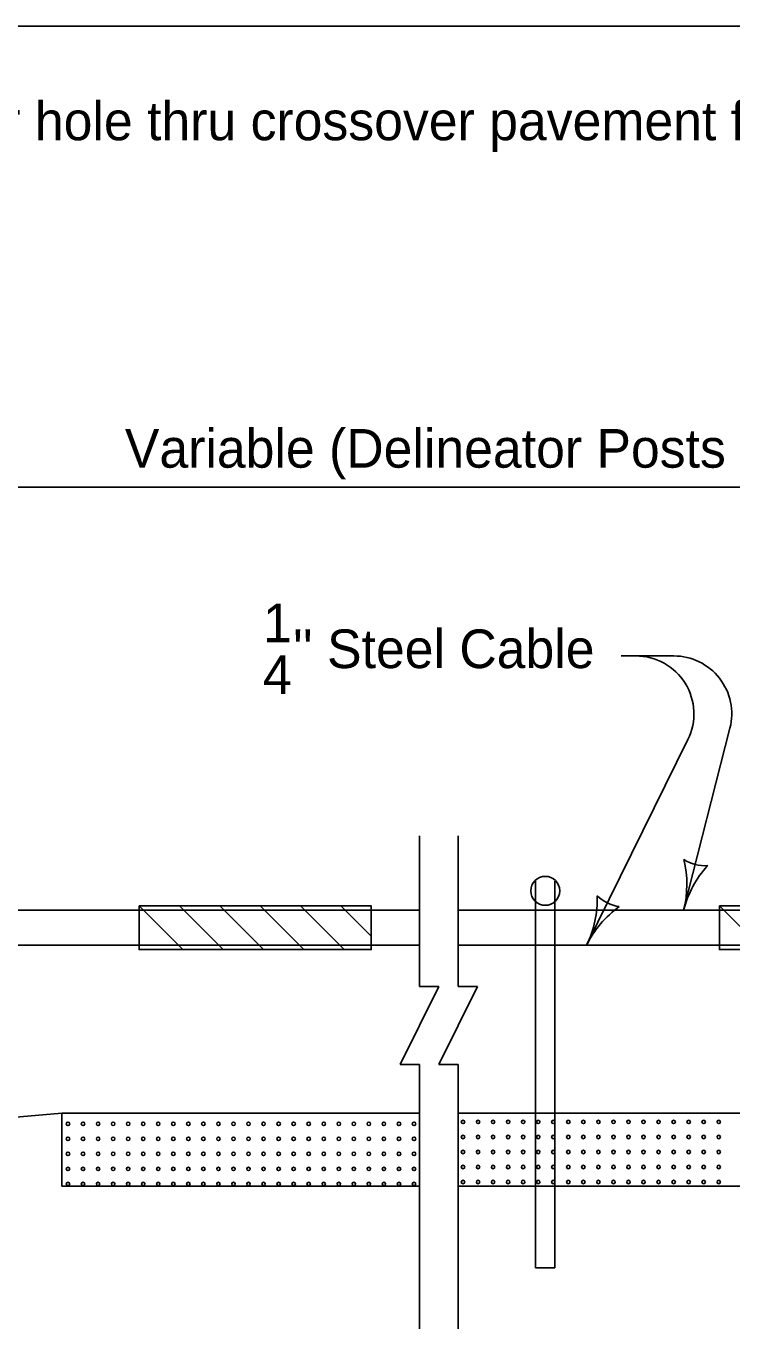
# Model space of a CAD drawing. Extents: x 228 to 3572, y -1307 to 1277.
# Drawn here: x 956 to 1248, y 35 to 575 of the extents above; entities that cross this region are included whole.
import ezdxf

# ---------------------------------------------------------------- set-up
doc = ezdxf.new("R2010")
doc.units = 0
doc.layers.add('dsnStdDimension', color=7, linetype='Continuous')
doc.layers.add('Level 2', color=7, linetype='Continuous')

msp = doc.modelspace()

# ---------------------------------------------------------------- linework, layer by layer
at = {"layer": 'dsnStdDimension'}
for p, q in [((690.89, 383.93), (2130.88, 383.93)), ((1202.29, 314.02), (1224.02, 314.02)), ((1228.12, 208.79), (1247.28, 284.11)), ((1187.96, 194.29), (1229.9, 279.42))]:
    msp.add_line(p, q, dxfattribs=at)
for centre, radius, start, end in [((1208.37, 290.02), 24, 333.7735, 90), ((1224.02, 290.02), 24, 345.7273, 90), ((1186.27, 219.43), 43.18, 345.7274, 13.7999), ((1269.97, 198.14), 43.18, 137.655, 165.7274), ((1237.05, 243.87), 16.68, 237.9941, 273.4608), ((1149.23, 213.37), 43.18, 333.7725, 1.8449), ((1203.96, 226.76), 16.68, 226.0391, 261.5058), ((1226.7, 175.2), 43.18, 125.7, 153.7725)]:
    msp.add_arc(centre, radius, start, end, dxfattribs=at)
at = {"layer": 'Level 2'}
for p, q in [((519.47, 574.71), (2276.26, 574.71)), ((1118.89, 239.58), (1118.89, 177.25)), ((1134.89, 239.58), (1134.89, 177.25)), ((1166.89, 220.79), (1166.89, 124.79)), ((1174.89, 220.79), (1174.89, 124.79)), ((1002.89, 210.54), (1020.99, 192.44)), ((1019.58, 210.54), (1037.68, 192.44)), ((1036.27, 210.54), (1054.37, 192.44)), ((1052.95, 210.54), (1071.05, 192.44)), ((1069.65, 210.54), (1087.75, 192.44)), ((1086.33, 210.54), (1098.87, 198)), ((458.89, 208.79), (1118.89, 208.79)), ((1134.89, 208.79), (1686.88, 208.79)), ((458.89, 194.29), (1118.89, 194.29)), ((1134.89, 194.29), (1686.88, 194.29)), ((1110.89, 144.94), (1126.89, 177.25)), ((1118.89, 177.25), (1126.89, 177.25)), ((1126.89, 144.94), (1142.89, 177.25)), ((1134.89, 177.25), (1142.89, 177.25)), ((1118.89, 144.94), (1110.89, 144.94)), ((1118.89, 144.94), (1118.89, 124.79)), ((1134.89, 144.94), (1126.89, 144.94)), ((1134.89, 144.94), (1134.89, 124.79)), ((970.89, 124.79), (810.89, 110.34)), ((970.89, 94.49), (970.89, 124.79)), ((970.89, 94.49), (970.89, 124.79)), ((970.89, 94.49), (970.89, 124.79)), ((970.89, 124.79), (1118.89, 124.79)), ((970.89, 124.79), (1118.89, 124.79)), ((1118.89, 124.79), (1118.89, 94.49)), ((1134.89, 94.49), (1134.89, 124.79)), ((1134.89, 124.79), (1686.88, 124.79)), ((1134.89, 124.79), (1686.88, 124.79)), ((1134.89, 124.79), (1686.88, 124.79)), ((1166.89, 124.79), (1166.89, 60.79)), ((1174.89, 124.79), (1174.89, 60.79)), ((1118.89, 94.49), (970.89, 94.49)), ((1118.89, 94.49), (1118.89, 35.46)), ((1134.89, 94.49), (1134.89, 35.46)), ((1686.88, 94.49), (1134.89, 94.49)), ((1166.89, 60.79), (1174.89, 60.79))]:
    msp.add_line(p, q, dxfattribs=at)
for points in [[(1002.89, 210.54), (1098.89, 210.54), (1098.89, 192.44), (1002.89, 192.44)], [(1002.89, 210.54), (1002.89, 192.44), (1020.99, 192.44)], [(1037.68, 192.44), (1054.37, 192.44), (1036.27, 210.54), (1019.58, 210.54)], [(1071.05, 192.44), (1087.75, 192.44), (1069.65, 210.54), (1052.95, 210.54)], [(1098.87, 198), (1098.87, 210.54), (1086.33, 210.54)], [(1242.89, 210.54), (1338.89, 210.54), (1338.89, 192.44), (1242.89, 192.44)], [(1242.89, 210.54), (1242.89, 192.44), (1260.99, 192.44)]]:
    msp.add_lwpolyline(points, close=True, dxfattribs=at)
for centre, radius in [((1170.89, 216.79), 6), ((973.48, 120.37), 0.711), ((979.71, 120.37), 0.711), ((985.93, 120.37), 0.711), ((992.15, 120.37), 0.711), ((998.37, 120.37), 0.711), ((1004.6, 120.37), 0.711), ((1010.82, 120.37), 0.711), ((1017.04, 120.37), 0.711), ((1023.26, 120.37), 0.711), ((1029.48, 120.37), 0.711), ((1035.71, 120.37), 0.711), ((1041.93, 120.37), 0.711), ((1048.15, 120.37), 0.711), ((1054.37, 120.37), 0.711), ((1060.6, 120.37), 0.711), ((1066.82, 120.37), 0.711), ((1073.04, 120.37), 0.711), ((1079.26, 120.37), 0.711), ((1085.49, 120.37), 0.711), ((1091.71, 120.37), 0.711), ((1097.93, 120.37), 0.711), ((1104.15, 120.37), 0.711), ((1110.38, 120.37), 0.711), ((1116.6, 120.37), 0.711), ((1136.87, 121.15), 0.711), ((1143.09, 121.15), 0.711), ((1149.31, 121.15), 0.711), ((1155.53, 121.15), 0.711), ((1161.76, 121.15), 0.711), ((1167.98, 121.15), 0.711), ((1174.2, 121.15), 0.711), ((1180.42, 121.15), 0.711), ((1186.64, 121.15), 0.711), ((1192.87, 121.15), 0.711), ((1199.09, 121.15), 0.711), ((1205.31, 121.15), 0.711), ((1211.53, 121.15), 0.711), ((1217.76, 121.15), 0.711), ((1223.98, 121.15), 0.711), ((1230.2, 121.15), 0.711), ((1236.42, 121.15), 0.711), ((1242.65, 121.15), 0.711), ((973.48, 114.14), 0.711), ((979.71, 114.14), 0.711), ((985.93, 114.14), 0.711), ((992.15, 114.14), 0.711), ((998.37, 114.14), 0.711), ((1004.6, 114.14), 0.711), ((1010.82, 114.14), 0.711), ((1017.04, 114.14), 0.711), ((1023.26, 114.14), 0.711), ((1029.48, 114.14), 0.711), ((1035.71, 114.14), 0.711), ((1041.93, 114.14), 0.711), ((1048.15, 114.14), 0.711), ((1054.37, 114.14), 0.711), ((1060.6, 114.14), 0.711), ((1066.82, 114.14), 0.711), ((1073.04, 114.14), 0.711), ((1079.26, 114.14), 0.711), ((1085.49, 114.14), 0.711), ((1091.71, 114.14), 0.711), ((1097.93, 114.14), 0.711), ((1104.15, 114.14), 0.711), ((1110.38, 114.14), 0.711), ((1116.6, 114.14), 0.711), ((1136.87, 114.92), 0.711), ((1143.09, 114.92), 0.711), ((1149.31, 114.92), 0.711), ((1155.53, 114.92), 0.711), ((1161.76, 114.92), 0.711), ((1167.98, 114.92), 0.711), ((1174.2, 114.92), 0.711), ((1180.42, 114.92), 0.711), ((1186.64, 114.92), 0.711), ((1192.87, 114.92), 0.711), ((1199.09, 114.92), 0.711), ((1205.31, 114.92), 0.711), ((1211.53, 114.92), 0.711), ((1217.76, 114.92), 0.711), ((1223.98, 114.92), 0.711), ((1230.2, 114.92), 0.711), ((1236.42, 114.92), 0.711), ((1242.65, 114.92), 0.711), ((973.48, 107.92), 0.711), ((979.71, 107.92), 0.711), ((985.93, 107.92), 0.711), ((992.15, 107.92), 0.711), ((998.37, 107.92), 0.711), ((1004.6, 107.92), 0.711), ((1010.82, 107.92), 0.711), ((1017.04, 107.92), 0.711), ((1023.26, 107.92), 0.711), ((1029.48, 107.92), 0.711), ((1035.71, 107.92), 0.711), ((1041.93, 107.92), 0.711), ((1048.15, 107.92), 0.711), ((1054.37, 107.92), 0.711), ((1060.6, 107.92), 0.711), ((1066.82, 107.92), 0.711), ((1073.04, 107.92), 0.711), ((1079.26, 107.92), 0.711), ((1085.49, 107.92), 0.711), ((1091.71, 107.92), 0.711), ((1097.93, 107.92), 0.711), ((1104.15, 107.92), 0.711), ((1110.38, 107.92), 0.711), ((1116.6, 107.92), 0.711), ((1136.87, 108.7), 0.711), ((1143.09, 108.7), 0.711), ((1149.31, 108.7), 0.711), ((1155.53, 108.7), 0.711), ((1161.76, 108.7), 0.711), ((1167.98, 108.7), 0.711), ((1174.2, 108.7), 0.711), ((1180.42, 108.7), 0.711), ((1186.64, 108.7), 0.711), ((1192.87, 108.7), 0.711), ((1199.09, 108.7), 0.711), ((1205.31, 108.7), 0.711), ((1211.53, 108.7), 0.711), ((1217.76, 108.7), 0.711), ((1223.98, 108.7), 0.711), ((1230.2, 108.7), 0.711), ((1236.42, 108.7), 0.711), ((1242.65, 108.7), 0.711), ((1136.87, 102.48), 0.711), ((1143.09, 102.48), 0.711), ((1149.31, 102.48), 0.711), ((1155.53, 102.48), 0.711), ((1161.76, 102.48), 0.711), ((1167.98, 102.48), 0.711), ((1174.2, 102.48), 0.711), ((1180.42, 102.48), 0.711), ((1186.64, 102.48), 0.711), ((1192.87, 102.48), 0.711), ((1199.09, 102.48), 0.711), ((1205.31, 102.48), 0.711), ((1211.53, 102.48), 0.711), ((1217.76, 102.48), 0.711), ((1223.98, 102.48), 0.711), ((1230.2, 102.48), 0.711), ((1236.42, 102.48), 0.711), ((1242.65, 102.48), 0.711), ((973.48, 101.7), 0.711), ((979.71, 101.7), 0.711), ((985.93, 101.7), 0.711), ((992.15, 101.7), 0.711), ((998.37, 101.7), 0.711), ((1004.6, 101.7), 0.711), ((1010.82, 101.7), 0.711), ((1017.04, 101.7), 0.711), ((1023.26, 101.7), 0.711), ((1029.48, 101.7), 0.711), ((1035.71, 101.7), 0.711), ((1041.93, 101.7), 0.711), ((1048.15, 101.7), 0.711), ((1054.37, 101.7), 0.711), ((1060.6, 101.7), 0.711), ((1066.82, 101.7), 0.711), ((1073.04, 101.7), 0.711), ((1079.26, 101.7), 0.711), ((1085.49, 101.7), 0.711), ((1091.71, 101.7), 0.711), ((1097.93, 101.7), 0.711), ((1104.15, 101.7), 0.711), ((1110.38, 101.7), 0.711), ((1116.6, 101.7), 0.711), ((973.48, 95.48), 0.711), ((979.71, 95.48), 0.711), ((985.93, 95.48), 0.711), ((992.15, 95.48), 0.711), ((998.37, 95.48), 0.711), ((1004.6, 95.48), 0.711), ((1010.82, 95.48), 0.711), ((1017.04, 95.48), 0.711), ((1023.26, 95.48), 0.711), ((1029.48, 95.48), 0.711), ((1035.71, 95.48), 0.711), ((1041.93, 95.48), 0.711), ((1048.15, 95.48), 0.711), ((1054.37, 95.48), 0.711), ((1060.6, 95.48), 0.711), ((1066.82, 95.48), 0.711), ((1073.04, 95.48), 0.711), ((1079.26, 95.48), 0.711), ((1085.49, 95.48), 0.711), ((1091.71, 95.48), 0.711), ((1097.93, 95.48), 0.711), ((1104.15, 95.48), 0.711), ((1110.38, 95.48), 0.711), ((1116.6, 95.48), 0.711), ((1136.87, 96.26), 0.711), ((1143.09, 96.26), 0.711), ((1149.31, 96.26), 0.711), ((1155.53, 96.26), 0.711), ((1161.76, 96.26), 0.711), ((1167.98, 96.26), 0.711), ((1174.2, 96.26), 0.711), ((1180.42, 96.26), 0.711), ((1186.64, 96.26), 0.711), ((1192.87, 96.26), 0.711), ((1199.09, 96.26), 0.711), ((1205.31, 96.26), 0.711), ((1211.53, 96.26), 0.711), ((1217.76, 96.26), 0.711), ((1223.98, 96.26), 0.711), ((1230.2, 96.26), 0.711), ((1236.42, 96.26), 0.711), ((1242.65, 96.26), 0.711)]:
    msp.add_circle(centre, radius, dxfattribs=at)

# ---------------------------------------------------------------- texts
at = {"layer": 'dsnStdDimension'}
for s, p in [("'' to 4'' diameter hole thru crossover pavement for each post.", (806.69, 527.46)), ('Variable (Delineator Posts equally spaced at approximately 15 feet center to center)', (997.02, 391.93)), ('1', (1054.11, 319.64)), ("'' Steel Cable", (1066.53, 308.97)), ('4', (1054.11, 298.31))]:
    msp.add_text(s, height=16, dxfattribs=at).set_placement(p)

doc.saveas('drawing.dxf')
